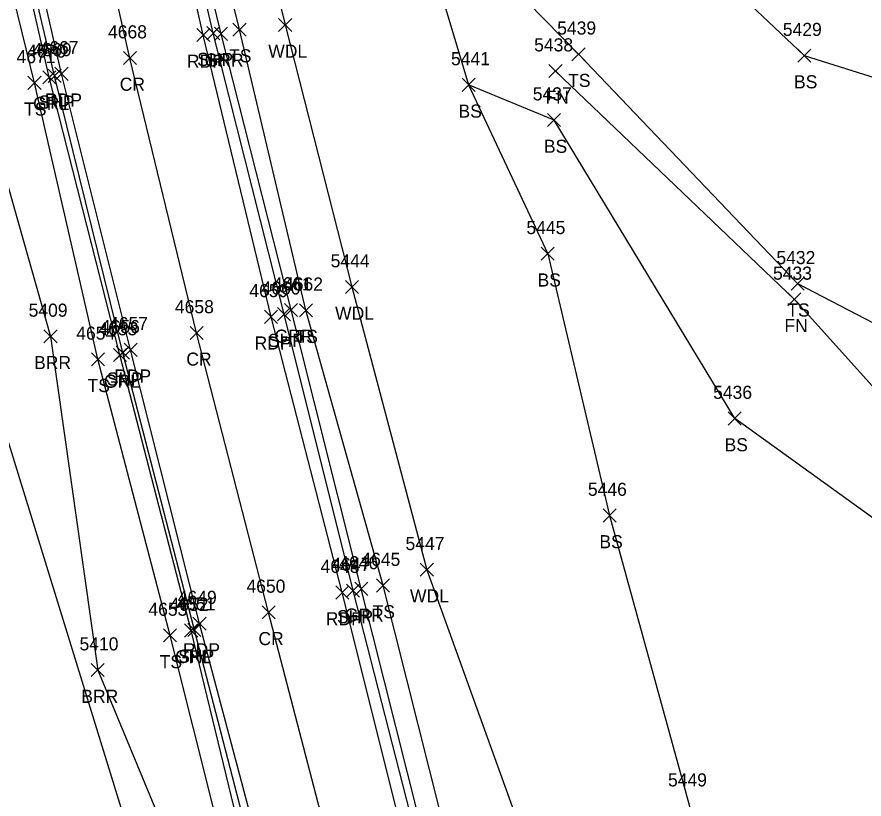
# Model space of a CAD drawing. Extents: x 1601151 to 1602912, y 499508 to 501770.
# Drawn here: x 1601466.6 to 1601596, y 500954.3 to 501073.7 of the extents above; entities that cross this region are included whole.
import ezdxf

# ---------------------------------------------------------------- set-up
doc = ezdxf.new("R2010")
doc.units = 0
for name, color, linetype in [('L_A', 7, 'Continuous'), ('L_I', 7, 'Continuous'), ('L_TIC', 7, 'Continuous'), ('LABL', 7, 'Continuous'), ('LAWA', 7, 'Continuous'), ('LELB', 7, 'Continuous'), ('LFNC', 7, 'Continuous'), ('P_A', 7, 'Continuous'), ('P_I', 7, 'Continuous'), ('P_TIC', 7, 'Continuous'), ('PET', 7, 'Continuous'), ('PRC', 7, 'Continuous'), ('PSP', 7, 'Continuous'), ('R_A', 7, 'Continuous'), ('R_I', 7, 'Continuous'), ('R_TIC', 7, 'Continuous'), ('RGR', 7, 'Continuous'), ('UCO', 7, 'Continuous')]:
    doc.layers.add(name, color=color, linetype=linetype)

msp = doc.modelspace()

# ---------------------------------------------------------------- linework, layer by layer
at = {"layer": 'L_TIC'}
for points in [[(1601499.63, 501070.76), (1601501.63, 501072.76)], [(1601501.63, 501070.76), (1601499.63, 501072.76)], [(1601506.6, 501071.47), (1601508.6, 501073.47)], [(1601508.6, 501071.47), (1601506.6, 501073.47)], [(1601551.42, 501067), (1601553.42, 501069)], [(1601553.42, 501067), (1601551.42, 501069)], [(1601585.9, 501066.79), (1601587.9, 501068.79)], [(1601587.9, 501066.79), (1601585.9, 501068.79)], [(1601547.9, 501064.43), (1601549.9, 501066.43)], [(1601549.9, 501064.43), (1601547.9, 501066.43)], [(1601468.31, 501062.64), (1601470.31, 501064.64)], [(1601470.31, 501062.64), (1601468.31, 501064.64)], [(1601534.63, 501062.32), (1601536.63, 501064.32)], [(1601536.63, 501062.32), (1601534.63, 501064.32)], [(1601534.63, 501062.32), (1601536.63, 501064.32)], [(1601536.63, 501062.32), (1601534.63, 501064.32)], [(1601547.69, 501056.95), (1601549.69, 501058.95)], [(1601549.69, 501056.95), (1601547.69, 501058.95)], [(1601546.72, 501036.54), (1601548.72, 501038.54)], [(1601548.72, 501036.54), (1601546.72, 501038.54)], [(1601584.91, 501031.96), (1601586.91, 501033.96)], [(1601586.91, 501031.96), (1601584.91, 501033.96)], [(1601516.81, 501031.47), (1601518.81, 501033.47)], [(1601518.81, 501031.47), (1601516.81, 501033.47)], [(1601584.39, 501029.58), (1601586.39, 501031.58)], [(1601586.39, 501029.58), (1601584.39, 501031.58)], [(1601584.39, 501029.58), (1601586.39, 501031.58)], [(1601586.39, 501029.58), (1601584.39, 501031.58)], [(1601509.78, 501027.92), (1601511.78, 501029.92)], [(1601511.78, 501027.92), (1601509.78, 501029.92)], [(1601470.76, 501023.93), (1601472.76, 501025.93)], [(1601472.76, 501023.93), (1601470.76, 501025.93)], [(1601478, 501020.43), (1601480, 501022.43)], [(1601480, 501020.43), (1601478, 501022.43)], [(1601575.29, 501011.39), (1601577.29, 501013.39)], [(1601577.29, 501011.39), (1601575.29, 501013.39)], [(1601556.17, 500996.59), (1601558.17, 500998.59)], [(1601558.17, 500996.59), (1601556.17, 500998.59)], [(1601528.25, 500988.31), (1601530.25, 500990.31)], [(1601530.25, 500988.31), (1601528.25, 500990.31)], [(1601521.55, 500985.9), (1601523.55, 500987.9)], [(1601523.55, 500985.9), (1601521.55, 500987.9)], [(1601489.02, 500978.28), (1601491.02, 500980.28)], [(1601491.02, 500978.28), (1601489.02, 500980.28)], [(1601477.97, 500972.99), (1601479.97, 500974.99)], [(1601479.97, 500972.99), (1601477.97, 500974.99)]]:
    msp.add_lwpolyline(points, dxfattribs=at)
at = {"layer": 'LABL'}
msp.add_lwpolyline([(1601436.15, 501158.98), (1601447.08, 501133.88), (1601451.13, 501097.99), (1601450.82, 501096.1), (1601461.24, 501061.82), (1601471.76, 501024.93), (1601478.97, 500973.99), (1601494.86, 500935.73), (1601497.29, 500914.1)], dxfattribs=at)
at = {"layer": 'LAWA'}
msp.add_lwpolyline([(1601499.96, 501103.39), (1601507.6, 501072.47), (1601517.81, 501032.47), (1601529.25, 500989.31), (1601544.54, 500946.97)], dxfattribs=at)
at = {"layer": 'LELB'}
for points in [[(1601519.45, 500871.01), (1601514.11, 500889.3), (1601500.79, 500936.5), (1601490.02, 500979.28), (1601479, 501021.43), (1601469.31, 501063.64), (1601460.33, 501100.01), (1601451.95, 501137.21), (1601445.85, 501173.31), (1601444.83, 501197.67), (1601441.57, 501231.33), (1601439.97, 501248.56), (1601437.52, 501260.47), (1601435.29, 501265.52), (1601431.82, 501269.24), (1601423.18, 501278.02), (1601413.06, 501283.54), (1601401.41, 501287.17), (1601388.07, 501289.76), (1601350.99, 501290.93), (1601302.64, 501293.09), (1601266.11, 501297.13)], [(1601550.27, 500878.88), (1601544.14, 500896.68), (1601533.21, 500944.65), (1601522.55, 500986.9), (1601510.78, 501028.92), (1601500.63, 501071.76), (1601491.58, 501108.11), (1601483.83, 501144.54), (1601478.65, 501178.38), (1601477.38, 501199.37), (1601474.08, 501219.68), (1601474.84, 501227.42), (1601475.18, 501230.5), (1601478.15, 501230.71)], [(1601480.04, 501230.08), (1601481.02, 501220.84), (1601484.49, 501191.95), (1601487.17, 501184.79), (1601490.69, 501172.33), (1601502.32, 501150.22), (1601523.31, 501131.22), (1601544.43, 501107.88), (1601586.9, 501067.79), (1601615.05, 501058.93)], [(1601502.32, 501150.22), (1601505.9, 501145.22), (1601526.18, 501094.76), (1601535.63, 501063.32), (1601547.72, 501037.54), (1601557.17, 500997.59), (1601569.36, 500953.23), (1601577.1, 500908.29), (1601582.38, 500892.08), (1601583.49, 500886.89), (1601585.02, 500882.65), (1601582.86, 500877.36), (1601583.41, 500861.09), (1601571.54, 500837.94)], [(1601614.22, 501018.25), (1601585.91, 501032.96), (1601552.42, 501068), (1601526.18, 501094.76)], [(1601617.5, 500982.72), (1601576.29, 501012.39), (1601548.69, 501057.95), (1601535.63, 501063.32)]]:
    msp.add_lwpolyline(points, dxfattribs=at)
at = {"layer": 'LFNC'}
for points in [[(1601585.39, 501030.58), (1601548.9, 501065.43)], [(1601585.39, 501030.58), (1601637.16, 500973.1), (1601642.99, 500962.95)]]:
    msp.add_lwpolyline(points, dxfattribs=at)
at = {"layer": 'P_TIC'}
for points in [[(1601494.1, 501069.93), (1601496.1, 501071.93)], [(1601496.1, 501069.93), (1601494.1, 501071.93)], [(1601495.62, 501070.21), (1601497.62, 501072.21)], [(1601497.62, 501070.21), (1601495.62, 501072.21)], [(1601482.89, 501066.42), (1601484.89, 501068.42)], [(1601484.89, 501066.42), (1601482.89, 501068.42)], [(1601471.39, 501063.7), (1601473.39, 501065.7)], [(1601473.39, 501063.7), (1601471.39, 501065.7)], [(1601472.44, 501064.01), (1601474.44, 501066.01)], [(1601474.44, 501064.01), (1601472.44, 501066.01)], [(1601504.44, 501026.92), (1601506.44, 501028.92)], [(1601506.44, 501026.92), (1601504.44, 501028.92)], [(1601506.44, 501027.32), (1601508.44, 501029.32)], [(1601508.44, 501027.32), (1601506.44, 501029.32)], [(1601493.07, 501024.46), (1601495.07, 501026.46)], [(1601495.07, 501024.46), (1601493.07, 501026.46)], [(1601481.81, 501021.43), (1601483.81, 501023.43)], [(1601483.81, 501021.43), (1601481.81, 501023.43)], [(1601482.99, 501021.88), (1601484.99, 501023.88)], [(1601484.99, 501021.88), (1601482.99, 501023.88)], [(1601516.98, 500985.13), (1601518.98, 500987.13)], [(1601518.98, 500985.13), (1601516.98, 500987.13)], [(1601515.32, 500984.83), (1601517.32, 500986.83)], [(1601517.32, 500984.83), (1601515.32, 500986.83)], [(1601504.08, 500981.8), (1601506.08, 500983.8)], [(1601506.08, 500981.8), (1601504.08, 500983.8)], [(1601493.52, 500980.09), (1601495.52, 500982.09)], [(1601495.52, 500980.09), (1601493.52, 500982.09)], [(1601492.73, 500979.11), (1601494.73, 500981.11)], [(1601494.73, 500979.11), (1601492.73, 500981.11)]]:
    msp.add_lwpolyline(points, dxfattribs=at)
at = {"layer": 'PET'}
for points in [[(1601544.22, 500876.26), (1601539.18, 500895.59), (1601526.95, 500943.37), (1601516.32, 500985.83), (1601505.44, 501027.92), (1601495.1, 501070.93), (1601487, 501107.14), (1601479.48, 501143.91), (1601474.16, 501178.21), (1601471.72, 501199.66), (1601469.2, 501232.53), (1601470.85, 501304.37), (1601475.76, 501342.26), (1601481.23, 501372.74), (1601489.71, 501419.6), (1601498.83, 501463.24), (1601509.83, 501514.72), (1601518.29, 501552.56), (1601529.19, 501602.72), (1601530.09, 501606.93), (1601533.57, 501622.36), (1601544.66, 501669.88)], [(1601523.48, 500870.9), (1601505.84, 500938.64), (1601494.52, 500981.09), (1601483.99, 501022.88), (1601473.44, 501065.01), (1601465.15, 501101.36), (1601457.99, 501138.15), (1601451.8, 501174.88), (1601449.08, 501198.01), (1601446.66, 501230.72), (1601445.89, 501253.39), (1601447.49, 501294.25), (1601451.95, 501334.78), (1601458.71, 501377.25), (1601475.95, 501468.24), (1601495.79, 501558.68), (1601503.76, 501593.61), (1601511.67, 501629.01)]]:
    msp.add_lwpolyline(points, dxfattribs=at)
at = {"layer": 'PRC'}
msp.add_lwpolyline([(1601533.3, 500873.43), (1601528.2, 500892.93), (1601515.88, 500940.69), (1601516.09, 500940.41), (1601505.08, 500982.8), (1601494.07, 501025.46), (1601483.89, 501067.42), (1601475.63, 501103.84), (1601468.62, 501140.87), (1601462.9, 501176.52), (1601460.41, 501198.76), (1601457.83, 501229.92), (1601457.03, 501256.97), (1601458.23, 501305.06), (1601463.89, 501343.75), (1601469.52, 501375.72), (1601487.67, 501465.73), (1601498.93, 501516.84), (1601507.24, 501554.65), (1601515.35, 501591.13), (1601523.43, 501627.3), (1601533.11, 501671.57)], dxfattribs=at)
at = {"layer": 'PSP'}
for points in [[(1601528.9, 500943.6), (1601517.98, 500986.13), (1601507.44, 501028.32), (1601496.62, 501071.21), (1601488.24, 501107.28), (1601480.68, 501144.12), (1601475.12, 501178.17), (1601472.51, 501199.52), (1601470.88, 501228.6), (1601471.76, 501230.34), (1601469.82, 501257.16), (1601471.6, 501304.23), (1601477.35, 501341.75), (1601482.3, 501372.17), (1601491.34, 501419.44), (1601500.56, 501462.85), (1601511.15, 501514.36), (1601520.07, 501552.2), (1601531.25, 501603.07), (1601534.57, 501619.48), (1601535.23, 501620.04), (1601536.15, 501623.42), (1601535.02, 501624.1), (1601546.22, 501669.66)], [(1601522.47, 500870.61), (1601521.44, 500871.56), (1601516.68, 500890.32), (1601504.63, 500938.05), (1601493.73, 500980.11), (1601482.81, 501022.43), (1601472.39, 501064.7), (1601463.73, 501101.18), (1601456.46, 501137.79), (1601450.78, 501174.54), (1601447.49, 501198.12), (1601444.54, 501230.82), (1601443.79, 501252.82), (1601439.57, 501267.27), (1601435, 501273.88), (1601425.87, 501282.16), (1601414.43, 501288.02), (1601402.06, 501290.61), (1601388.18, 501292.3), (1601350.65, 501293.39), (1601302.63, 501296.39), (1601266.65, 501300.03)]]:
    msp.add_lwpolyline(points, dxfattribs=at)
at = {"layer": 'R_TIC'}
for points in [[(1601496.81, 501070.11), (1601498.81, 501072.11)], [(1601498.81, 501070.11), (1601496.81, 501072.11)], [(1601470.56, 501063.48), (1601472.56, 501065.48)], [(1601472.56, 501063.48), (1601470.56, 501065.48)], [(1601507.51, 501027.96), (1601509.51, 501029.96)], [(1601509.51, 501027.96), (1601507.51, 501029.96)], [(1601481.37, 501021.09), (1601483.37, 501023.09)], [(1601483.37, 501021.09), (1601481.37, 501023.09)], [(1601518.23, 500985.39), (1601520.23, 500987.39)], [(1601520.23, 500985.39), (1601518.23, 500987.39)], [(1601492.24, 500979.03), (1601494.24, 500981.03)], [(1601494.24, 500979.03), (1601492.24, 500981.03)]]:
    msp.add_lwpolyline(points, dxfattribs=at)
at = {"layer": 'RGR'}
for points in [[(1601521.19, 500871.52), (1601516.17, 500890.13), (1601503.52, 500937.63), (1601493.24, 500980.03), (1601482.37, 501022.09), (1601471.56, 501064.48), (1601463.23, 501100.71), (1601455.93, 501137.47), (1601449.86, 501174.24), (1601446.89, 501198.08), (1601443.46, 501231.31), (1601442.27, 501248.6), (1601440.18, 501261.03), (1601437.51, 501266.72), (1601434.07, 501271.66), (1601424.7, 501280.1), (1601413.85, 501286.21), (1601401.7, 501289.17), (1601388.07, 501289.76)], [(1601542.08, 500896.22), (1601529.83, 500944.35), (1601519.23, 500986.39), (1601508.51, 501028.96), (1601497.81, 501071.11), (1601488.92, 501107.46), (1601481.8, 501144.25), (1601476.28, 501178.37), (1601473.71, 501199.44), (1601474.08, 501219.68)]]:
    msp.add_lwpolyline(points, dxfattribs=at)
at = {"layer": 'UCO'}
msp.add_lwpolyline([(1601766.65, 501489.44), (1601471.02, 501503.9), (1601438.7, 501339.97), (1601411.28, 501184.01), (1601489.93, 500928.89)], dxfattribs=at)

# ---------------------------------------------------------------- texts
at = {"layer": 'L_A'}
for s, p in [('TS', (1601499.04, 501066.76)), ('WDL', (1601505.02, 501067.47)), ('TS', (1601550.83, 501063)), ('BS', (1601585.34, 501062.79)), ('FN', (1601547.38, 501060.43)), ('TS', (1601467.72, 501058.64)), ('BS', (1601534.08, 501058.32)), ('BS', (1601534.08, 501058.32)), ('BS', (1601547.13, 501052.95)), ('BS', (1601546.16, 501032.54)), ('TS', (1601584.32, 501027.96)), ('WDL', (1601515.23, 501027.47)), ('FN', (1601583.87, 501025.58)), ('FN', (1601583.87, 501025.58)), ('TS', (1601509.19, 501023.92)), ('BRR', (1601469.25, 501019.93)), ('TS', (1601477.41, 501016.43)), ('BS', (1601574.73, 501007.39)), ('BS', (1601555.61, 500992.59)), ('WDL', (1601526.67, 500984.31)), ('TS', (1601520.96, 500981.9)), ('TS', (1601488.43, 500974.28)), ('BRR', (1601476.46, 500968.99))]:
    msp.add_text(s, height=2, dxfattribs=at).set_placement(p)
at = {"layer": 'L_I'}
for s, p in [('5439', (1601549.16, 501071)), ('5429', (1601583.63, 501070.79)), ('5438', (1601545.64, 501068.43)), ('4671', (1601466.57, 501066.64)), ('5441', (1601532.94, 501066.32)), ('5441', (1601532.94, 501066.32)), ('5437', (1601545.43, 501060.95)), ('5445', (1601544.46, 501040.54)), ('5432', (1601582.65, 501035.96)), ('5444', (1601514.55, 501035.47)), ('5433', (1601582.13, 501033.58)), ('5433', (1601582.13, 501033.58)), ('4662', (1601507.43, 501031.92)), ('5409', (1601468.41, 501027.93)), ('4654', (1601475.69, 501024.43)), ('5436', (1601572.98, 501015.39)), ('5446', (1601553.85, 501000.59)), ('5447', (1601525.99, 500992.31)), ('4645', (1601519.24, 500989.9)), ('4653', (1601486.71, 500982.28)), ('5410', (1601476.19, 500976.99)), ('5449', (1601566.09, 500956.23)), ('5449', (1601566.09, 500956.23)), ('5449', (1601566.09, 500956.23))]:
    msp.add_text(s, height=2, dxfattribs=at).set_placement(p)
at = {"layer": 'P_A'}
for s, p in [('RDP', (1601492.59, 501065.93)), ('SHP', (1601494.16, 501066.21)), ('CR', (1601482.33, 501062.42)), ('SHP', (1601469.93, 501059.7)), ('RDP', (1601470.92, 501060.01)), ('RDP', (1601502.93, 501022.92)), ('SHP', (1601504.97, 501023.32)), ('CR', (1601492.5, 501020.46)), ('RDP', (1601481.48, 501017.88)), ('SHP', (1601480.35, 501017.43)), ('RDP', (1601513.81, 500980.83)), ('SHP', (1601515.52, 500981.13)), ('CR', (1601503.52, 500977.8)), ('RDP', (1601492, 500976.09)), ('SHP', (1601491.27, 500975.11))]:
    msp.add_text(s, height=2, dxfattribs=at).set_placement(p)
at = {"layer": 'P_I'}
for s, p in [('4668', (1601480.54, 501070.42)), ('4667', (1601470.08, 501068.01)), ('4669', (1601469.03, 501067.7)), ('4659', (1601502.13, 501030.92)), ('4660', (1601504, 501031.32)), ('4658', (1601490.76, 501028.46)), ('4656', (1601479.45, 501025.43)), ('4657', (1601480.69, 501025.88)), ('4647', (1601514.67, 500989.13)), ('4648', (1601513.01, 500988.83)), ('4650', (1601501.69, 500985.8)), ('4649', (1601491.2, 500984.09)), ('4651', (1601490.99, 500983.11))]:
    msp.add_text(s, height=2, dxfattribs=at).set_placement(p)
at = {"layer": 'R_A'}
for s, p in [('GRR', (1601495.3, 501066.11)), ('GRL', (1601469.1, 501059.48)), ('GRR', (1601506, 501023.96)), ('GRL', (1601479.91, 501017.09)), ('GRR', (1601516.72, 500981.39)), ('GRL', (1601490.79, 500975.03))]:
    msp.add_text(s, height=2, dxfattribs=at).set_placement(p)
at = {"layer": 'R_I'}
for s, p in [('4670', (1601468.17, 501067.48)), ('4661', (1601505.72, 501031.96)), ('4655', (1601479.06, 501025.09)), ('4646', (1601515.87, 500989.39)), ('4652', (1601489.94, 500983.03))]:
    msp.add_text(s, height=2, dxfattribs=at).set_placement(p)

doc.saveas('drawing.dxf')
